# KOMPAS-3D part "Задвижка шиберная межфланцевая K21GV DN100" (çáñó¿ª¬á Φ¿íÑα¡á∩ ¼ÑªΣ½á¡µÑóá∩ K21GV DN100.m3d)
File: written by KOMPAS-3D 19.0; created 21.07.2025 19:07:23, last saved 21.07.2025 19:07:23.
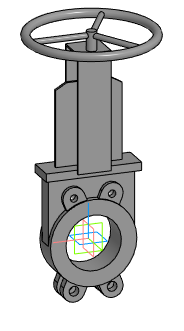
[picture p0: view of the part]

Document properties: Автор: Евгений; Полное имя файла: E:\Dendor Работа Сачек\3D для проектировщиков\2.3 Тип K21GV. Задвижка шиберная межфланцевая\stp_Задвижка шиберная K21GV DN50-400 с маховиком\Задвижка шиберная межфланцевая K21GV DN100.m3d

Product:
- Part/product: Задвижка шиберная межфланцевая K21GV DN100

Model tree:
1. Операция без истории:1  (labels: Задвижка шиберная межфланцевая K21GV DN100)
